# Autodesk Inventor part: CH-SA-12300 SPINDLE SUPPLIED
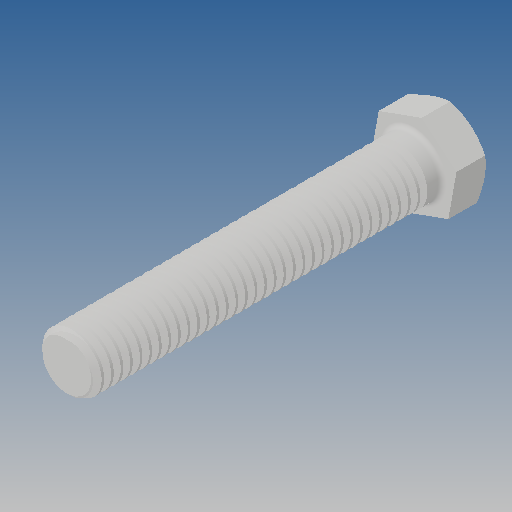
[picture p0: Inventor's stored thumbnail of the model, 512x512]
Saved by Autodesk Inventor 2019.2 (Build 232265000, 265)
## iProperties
Created: 2012-09
Part Number: CH-SA-12300 SPINDLE SUPPLIED
Material: Ogólny
Document SubType Name: Modeling
Designer: CADENGINEERING4
Density: 1 g/cm^3
Appearance: Domyślna
Author: CADENGINEERING4
Revision Number: ÈÎºÎ
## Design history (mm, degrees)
feature "ÇÐ³ý-É¨Ãè4"
node "Bryła1"
